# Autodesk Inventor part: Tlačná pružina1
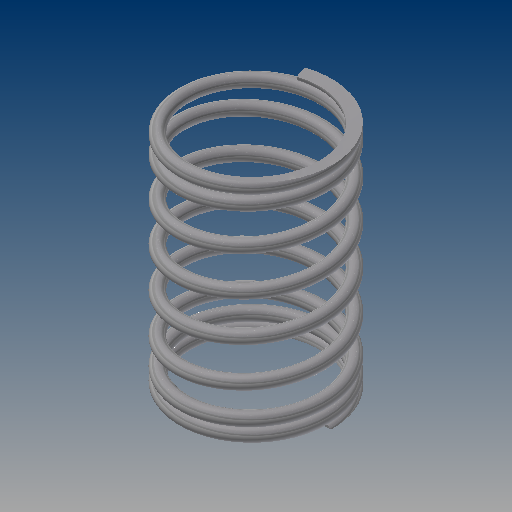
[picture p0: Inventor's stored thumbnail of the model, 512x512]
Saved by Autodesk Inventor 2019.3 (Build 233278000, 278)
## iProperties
Created: 2019-05
Part Number: Tlačná pružina1
Material: Steel
Document SubType Name: Modeling
Designer: B-hon
Density: 2.18 g/cm^3
Appearance: Steel
CustomPartVersion: 1
Author: B-hon
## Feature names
1. Main Coil Feature(R)
2. Počáteční přechodová spirála 1 (pravá)
3. Coil  Start Transition 2(R)
4. Coil  Start Transition 3(R)
5. Coil  Start Transition 4(R)
6. Spirála počátečních ukončení (pravá)
7. Prvek počátečního řezu (pravý) [Extrusion]
8. Koncová přechodová spirála 1 (pravá)
9. Koncová přechodová spirála 2 (pravá)
10. Koncová přechodová spirála 3 (pravá)
11. Koncová přechodová spirála 4 (pravá)
12. Koncová spirála (pravá)
13. Prvek koncového řezu (pravý) [Extrusion]
14. Prvek řezu rovných konců 1 (pravý) [Extrusion]
15. Plain Ends Cut  2(R) [Extrusion]
16. Main Coil Feature(L)
17. Počáteční přechodová spirála 1 (levá)
18. Počáteční přechodová spirála 2 (levá)
19. Počáteční přechodová spirála 3 (levá)
20. Počáteční přechodová spirála 4 (levá)
21. Spirála počátečních zakončení (levá)
22. Prvek počátečního řezu (levý) [Extrusion]
23. Koncová přechodová spirála 1 (levá)
24. Koncová přechodová spirála 2 (levá)
25. Koncová přechodová spirála 3 (levá)
26. Koncová přechodová spirála 4 (levá)
27. Koncová spirála (levá)
28. Koncový prvek řezu (levý) [Extrusion]
29. Cut Plain Ends Cut 1(L) [Extrusion]
30. Cut Plain Ends Cut 2(L) [Extrusion]
## Parameters: d0 = 0.25 mm, da_d = 1 mm, da_n = 58 mm, da_ti = 3.11399 mm, da_nz1 = 15 mm, spiral_Angle = 0.89868 mm, d2 = 3.11399 mm, d4 = 40.5 mm, d5 = 0, d6 = 90 deg, d7 = 90 deg, d8 = 0, d9 = 0, d12 = 2.34457 mm, d13 = -3.04377 mm, d14 = 1 mm, d15 = 0, d16 = 2.58549 mm, d18 = 2.5 mm, d19 = 0, d20 = 90 deg, d21 = 90 deg, d22 = 0, d23 = 0, d24 = 2.057 mm, d26 = 2.5 mm, d27 = 0, d28 = 90 deg, d29 = 90 deg, d30 = 0, d31 = 0, d32 = 1.5285 mm, d34 = 2.5 mm, d35 = 0, d36 = 90 deg, d37 = 90 deg, d38 = 0, d39 = 0, d40 = 1 mm, d42 = 2.5 mm, d43 = 0, d44 = 90 deg, d45 = 90 deg, d46 = 0, d47 = 0, d48 = 2.58549 mm, d50 = 1.875 mm, d51 = 0, d52 = 90 deg, d53 = 90 deg, d54 = 0, d55 = 0, d56 = 2.057 mm, d58 = 1.875 mm, d59 = 0, d60 = 90 deg, d61 = 90 deg, d62 = 0, d63 = 0, d64 = 1.5285 mm, d66 = 1.875 mm, d67 = 0, d68 = 90 deg, d69 = 90 deg, d70 = 0, d71 = 0, d72 = 1 mm, d74 = 1.875 mm, d75 = 0, d76 = 90 deg, d77 = 90 deg, d78 = 0, d79 = 0, End_Pitch = 1.00405 mm, d82 = 15 mm, d83 = 0, d84 = 90 deg, d85 = 90 deg, d86 = 0, d87 = 0, d88 = 1.00405 mm, d91 = 0, d92 = 90 deg, d93 = 90 deg, d94 = 0, d95 = 0, d96 = 12 mm, d97 = 1.00405 mm, d98 = 0, d99 = 12 mm, d100 = 1.00405 mm, d101 = 0, d102 = 0, d103 = 0, d104 = 0, d105 = 0, d106 = 0, d108 = 0, d112 = 0, d113 = 0, d114 = 0, const_zero = 0, Not_rightdir = 0, d121 = 0.25506 mm, d131 = 0, d132 = 0, d133 = 0, d134 = 0, d135 = 0.25 mm, d137 = 3.11399 mm, d139 = 40.5 mm, d140 = 0, d141 = 90 deg, d142 = 90 deg, d143 = 0, d144 = 0, d145 = 2.34457 mm, d146 = -3.04377 mm, d147 = 0.25506 mm, d148 = 0.00404 mm, d149 = 1 mm, d150 = 0, d151 = 0, d152 = 2.58549 mm, d154 = 2.5 mm, d155 = 0, d156 = 90 deg, d157 = 90 deg, d158 = 0, d159 = 0, d160 = 2.057 mm, d162 = 2.5 mm, d163 = 0, d164 = 90 deg, d165 = 90 deg, d166 = 0, d167 = 0, d168 = 1.5285 mm, d170 = 2.5 mm, d171 = 0, d172 = 90 deg, d173 = 90 deg, d174 = 0, d175 = 0, d176 = 1 mm, d178 = 2.5 mm, d179 = 0, d180 = 90 deg, d181 = 90 deg, d182 = 0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
